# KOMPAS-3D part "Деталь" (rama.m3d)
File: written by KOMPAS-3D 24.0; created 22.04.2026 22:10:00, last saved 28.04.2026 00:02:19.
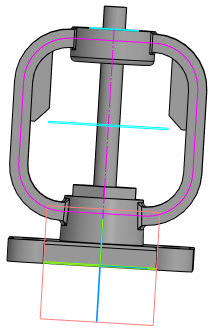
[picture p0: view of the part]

Document properties: Автор: mrdid; Полное имя файла: C:\Работа\ГОТОВЫЕ ИСХОДНИКИ\VSO2130M-F-S Клапан запорный сальниковый DN.ru Ду15-100 Ру40\исходные материалы\DN32\rama.m3d

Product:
- Part/product: Деталь
    Масса: 1.052379

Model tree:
1. Эскиз:2  (with: Ребро.Элемент выдавливания:14)
2. Элемент выдавливания:1
     Расстояние 1 = 10
3. Эскиз:3  (with: Грань.Элемент выдавливания:1, Ребро.Элемент выдавливания:1)
4. Элемент выдавливания:2
     Расстояние 2 = 10
5. Эскиз:4  (with: Грань.Элемент выдавливания:1)
6. Элемент выдавливания:3
     Угол 1 = -3
7. Эскиз:5  (with: Грань.Элемент выдавливания:3, Ребро.Элемент выдавливания:3)
8. Элемент выдавливания:4
9. Эскиз:23  (with: Грань.Элемент выдавливания:4, Ребро.Элемент выдавливания:4)
10. Элемент выдавливания:21  (labels: Деталь2; Грань.Твердое тело1)
     Расстояние 1 = 79.4875
11. Эскиз:7  (with: Грань.Элемент выдавливания:4, Ребро.Элемент выдавливания:3)
12. Элемент выдавливания:6  (with: Грань.Элемент выдавливания:3)
     Расстояние 2 = 5
13. Смещенная плоскость:4  (labels: Деталь2; Грань.Твердое тело1)
     Расстояние = 10
14. Эскиз:24  (with: Ребро.Элемент выдавливания:3)
15. Элемент выдавливания:22
     Расстояние 2 = 15
16. Эскиз:25  (with: Ребро.Элемент выдавливания:3)
17. Эскиз:26  (with: Ребро.Элемент выдавливания:3)
18. Элемент по траектории:1
     Длина траектории = 272.639
19. Скругление:8  (with: Ребро.Элемент по траектории:1)
     Радиус = 2
20. Скругление:9  (with: Ребро.Элемент по траектории:1)
     Радиус = 1
21. Смещенная плоскость:5  (with: Грань.Элемент выдавливания:1)
22. Эскиз:27  (with: Вершина.Элемент по траектории:1)
23. Элемент выдавливания:23  (with: Грань.Элемент выдавливания:22)
     Расстояние 1 = 32.4875; Смещение 1 = 5
24. Скругление:1  (with: Ребро.Элемент выдавливания:1)
     Радиус = 1.5
25. Скругление:10  (with: Ребро.Элемент выдавливания:22)
     Радиус = 2
26. Фаска:1  (with: Ребро.Элемент выдавливания:23)
     Угол = 45; Длина 1 = 6; Длина 2 = 6
27. Массив по концентрической сетке:1  (with: Элемент выдавливания:2, Эскиз:3)  (labels: Клапан запорный DN.ru Ду32 Ру40)  (4 pattern instances)
     Шаг 2 = 360

Expressions: DN/2; DN/4; H/4
Referenced files in C:\Работа\ГОТОВЫЕ ИСХОДНИКИ\VSO2130M-F-S Клапан запорный сальниковый DN.ru Ду15-100 Ру40\исходные материалы\DN32\: VSO2130M-F-S Клапан запорный DN.ru Ду32 Ру40.a3d
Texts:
  DN+5
  Ось Y.Начало координат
